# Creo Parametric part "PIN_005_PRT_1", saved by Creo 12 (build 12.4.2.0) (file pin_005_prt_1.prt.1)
Units: Custom; MM, KILOGRAM, SECS

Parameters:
  PTC_WM_ITERATION = "0"
  PTC_WM_VERSION = "-.0"
  PTC_WM_LIFECYCLE_STATE = "In Work"
  PTC_WM_LIFECYCLE = "MO_CADDocument"
  PTC_WM_CREATED_BY = "Maximilian Roepper (Z0017RMS: MO)"
  PTC_WM_CREATED_ON = "18-Sep-26 11:36:42 AM"
  PTC_WM_MODIFIED_BY = "Maximilian Roepper (Z0017RMS: MO)"
  PTC_WM_MODIFIED_ON = "18-Sep-26 11:36:46 AM"
  PDMLINKNUMBER = "PDM000071455327"
  PTC_WM_NAME = "pin_005_prt_1.prt"
  PTC_WM_NUMBER = "PDM000071455327"

Other parameters: WEIGHT, WEIGHT_FACTOR, WEIGHT_ADD, _MASS_TEMP, _DIFF_TEMP, MC_ERRORS, SUPPLIER

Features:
  1. coordinate system
  2. datum plane "PRT_YZ"
  3. datum plane "PRT_XY"
  4. datum plane "PRT_XZ"
  5. coordinate system
  6. datum axis
  7. datum axis
  8. datum axis
  9. coordinate system
  10. imported feature
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
Other named items: PRT, SIEMENS_MO, DRW_VIEW_ORG, PRT_X, PRT_Y, PRT_Z, CS0, ROUGH_GROB

Layers: 00_STD_CSYS-KSYS, 01_STD_PLANES-EBENEN, 02_STD_AXES-ACHSEN, 03_STD_CSYS-KSYS, 24_IMPORT_FEAT-IMPORT_KE

Surfaces: 9 plane, 1 cylinder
